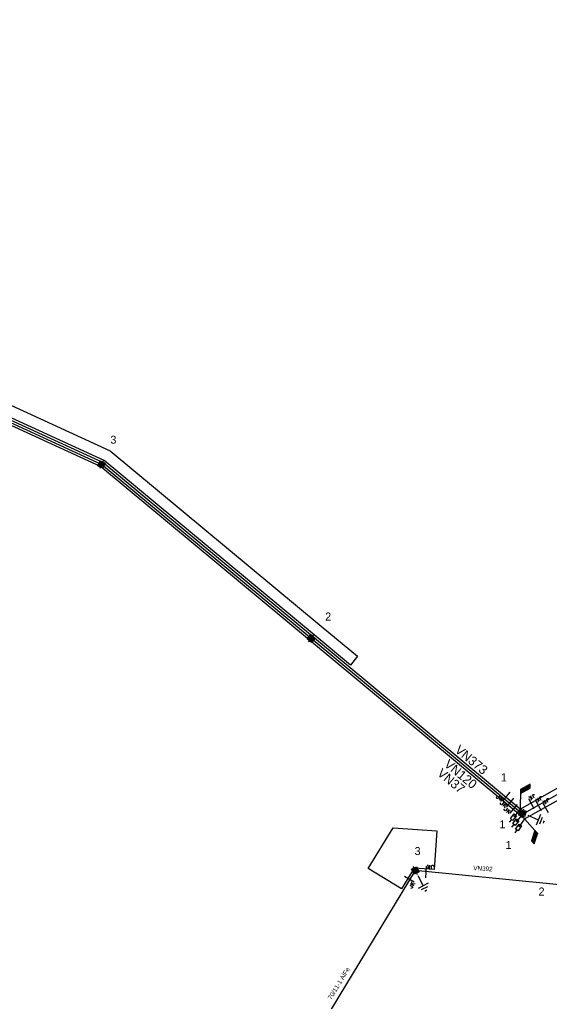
# Model space of a CAD drawing. Extents: x -540340 to -537226, y -1183949 to -1180375.
# Drawn here: x -537658.9 to -537543.1, y -1180690 to -1180475.4 of the extents above; entities that cross this region are included whole.
import ezdxf

# ---------------------------------------------------------------- set-up
doc = ezdxf.new("R2010")
doc.units = 0
for name, color, linetype in [('Vrstva 1', 7, 'Continuous'), ('Vrstva 11', 7, 'Continuous'), ('Vrstva 12', 7, 'Continuous'), ('Vrstva 13', 7, 'Continuous'), ('Vrstva 14', 7, 'Continuous'), ('Vrstva 15', 7, 'Continuous'), ('Vrstva 16', 7, 'Continuous'), ('Vrstva 18', 7, 'Continuous'), ('Vrstva 2', 7, 'Continuous'), ('Vrstva 3', 7, 'Continuous'), ('Vrstva 35', 7, 'Continuous'), ('Vrstva 50', 7, 'Continuous'), ('Vrstva 51', 7, 'Continuous')]:
    doc.layers.add(name, color=color, linetype=linetype)

msp = doc.modelspace()

# ---------------------------------------------------------------- linework, layer by layer
at = {"layer": 'Vrstva 1'}
for points in [[(-537549.42, -1180647.98), (-537524.99, -1180634.15)], [(-537548.92, -1180649.04), (-537524.29, -1180635.07)], [(-537548.49, -1180650.05), (-537523.4, -1180636.11)], [(-537531.99, -1180665.41), (-537572.36, -1180661.38), (-537627.26, -1180751.9)]]:
    msp.add_lwpolyline(points, dxfattribs=at)
at = {"layer": 'Vrstva 11'}
for p, q in [((-537549.38, -1180644.32), (-537547.27, -1180643.15)), ((-537549.38, -1180644.37), (-537547.27, -1180643.2)), ((-537549.38, -1180644.43), (-537547.27, -1180643.26)), ((-537549.38, -1180644.49), (-537547.27, -1180643.32)), ((-537549.37, -1180643.74), (-537547.26, -1180642.57)), ((-537549.37, -1180643.8), (-537547.26, -1180642.63)), ((-537549.37, -1180643.86), (-537547.26, -1180642.68)), ((-537549.37, -1180643.91), (-537547.26, -1180642.74)), ((-537549.37, -1180643.97), (-537547.26, -1180642.8)), ((-537549.37, -1180644.03), (-537547.26, -1180642.86)), ((-537549.37, -1180644.09), (-537547.26, -1180642.91)), ((-537549.37, -1180644.14), (-537547.26, -1180642.97)), ((-537549.37, -1180644.2), (-537547.26, -1180643.03)), ((-537549.37, -1180644.26), (-537547.26, -1180643.09)), ((-537549.37, -1180643.68), (-537549.01, -1180643.48)), ((-537546.17, -1180652.66), (-537546.94, -1180654.95)), ((-537546.13, -1180652.7), (-537546.9, -1180654.99)), ((-537546.09, -1180652.74), (-537546.86, -1180655.03)), ((-537546.06, -1180652.79), (-537546.82, -1180655.08)), ((-537546.02, -1180652.83), (-537546.79, -1180655.12)), ((-537545.98, -1180652.87), (-537546.75, -1180655.16)), ((-537545.94, -1180652.92), (-537546.71, -1180655.21)), ((-537545.9, -1180652.96), (-537546.67, -1180655.25)), ((-537545.86, -1180653), (-537546.63, -1180655.29)), ((-537545.83, -1180653.05), (-537546.6, -1180655.33)), ((-537545.79, -1180653.09), (-537546.56, -1180655.38)), ((-537545.75, -1180653.13), (-537546.52, -1180655.42)), ((-537545.71, -1180653.17), (-537546.48, -1180655.46)), ((-537545.67, -1180653.22), (-537546.44, -1180655.51)), ((-537545.64, -1180653.26), (-537545.77, -1180653.65))]:
    msp.add_line(p, q, dxfattribs=at)
for points in [[(-537549.37, -1180643.68), (-537549.42, -1180647.98)], [(-537545.63, -1180653.26), (-537548.49, -1180650.05)]]:
    msp.add_lwpolyline(points, dxfattribs=at)
for points in [[(-537547.25, -1180642.52), (-537549.37, -1180643.68), (-537549.38, -1180644.54), (-537547.27, -1180643.37)], [(-537546.41, -1180655.55), (-537545.63, -1180653.26), (-537546.21, -1180652.62), (-537546.97, -1180654.91)]]:
    msp.add_lwpolyline(points, close=True, dxfattribs=at)
at = {"layer": 'Vrstva 13'}
for points in [[(-537641.74, -1180572.92), (-537641.23, -1180571.8)], [(-537640.63, -1180573.43), (-537641.74, -1180572.92)], [(-537641.54, -1180572.85), (-537641.16, -1180572.01)], [(-537640.71, -1180573.23), (-537641.54, -1180572.85)], [(-537641.34, -1180572.76), (-537641.08, -1180572.21)], [(-537640.78, -1180573.02), (-537641.34, -1180572.76)], [(-537641.19, -1180573.17), (-537641.34, -1180573.51)], [(-537641.23, -1180571.8), (-537640.12, -1180572.31)], [(-537641.16, -1180572.01), (-537640.32, -1180572.4)], [(-537641.12, -1180572.67), (-537641, -1180572.39)], [(-537640.85, -1180572.8), (-537641.12, -1180572.67)], [(-537641.08, -1180572.21), (-537640.52, -1180572.46)], [(-537641, -1180572.39), (-537640.72, -1180572.52)], [(-537640.72, -1180572.52), (-537640.85, -1180572.8)], [(-537640.52, -1180572.46), (-537640.78, -1180573.02)], [(-537640.32, -1180572.4), (-537640.71, -1180573.23)], [(-537640.67, -1180572.06), (-537640.52, -1180571.72)], [(-537640.12, -1180572.31), (-537640.63, -1180573.43)], [(-537596.01, -1180610.73), (-537595.22, -1180609.78)], [(-537595.8, -1180610.72), (-537595.21, -1180610.01)], [(-537595.22, -1180609.78), (-537594.28, -1180610.57)], [(-537595.21, -1180610.01), (-537594.5, -1180610.6)], [(-537594.75, -1180610.18), (-537594.51, -1180609.89)], [(-537595.06, -1180611.51), (-537596.01, -1180610.73)], [(-537595.09, -1180611.31), (-537595.8, -1180610.72)], [(-537595.54, -1180611.12), (-537595.78, -1180611.41)], [(-537595.58, -1180610.69), (-537595.18, -1180610.22)], [(-537595.1, -1180611.08), (-537595.58, -1180610.69)], [(-537595.35, -1180610.65), (-537595.15, -1180610.42)], [(-537595.11, -1180610.85), (-537595.35, -1180610.65)], [(-537595.18, -1180610.22), (-537594.71, -1180610.61)], [(-537595.15, -1180610.42), (-537594.92, -1180610.61)], [(-537594.92, -1180610.61), (-537595.11, -1180610.85)], [(-537594.71, -1180610.61), (-537595.1, -1180611.08)], [(-537594.5, -1180610.6), (-537595.09, -1180611.31)], [(-537594.28, -1180610.57), (-537595.06, -1180611.51)], [(-537549.7, -1180649.25), (-537549.34, -1180648.07)], [(-537549.51, -1180649.16), (-537549.24, -1180648.27)], [(-537549.34, -1180648.07), (-537548.16, -1180648.43)], [(-537549.31, -1180649.04), (-537549.13, -1180648.46)], [(-537549.24, -1180648.27), (-537548.36, -1180648.54)], [(-537549.13, -1180648.46), (-537548.55, -1180648.64)], [(-537549.12, -1180648.92), (-537549.03, -1180648.63)], [(-537549.03, -1180648.63), (-537548.73, -1180648.72)], [(-537548.73, -1180648.72), (-537548.82, -1180649.01)], [(-537548.75, -1180648.25), (-537548.64, -1180647.89)], [(-537548.55, -1180648.64), (-537548.73, -1180649.22)], [(-537548.36, -1180648.54), (-537548.63, -1180649.42)], [(-537548.16, -1180648.43), (-537548.52, -1180649.61)], [(-537548.52, -1180649.61), (-537549.7, -1180649.25)], [(-537548.63, -1180649.42), (-537549.51, -1180649.16)], [(-537548.73, -1180649.22), (-537549.31, -1180649.04)], [(-537549.11, -1180649.43), (-537549.22, -1180649.79)], [(-537548.82, -1180649.01), (-537549.12, -1180648.92)], [(-537573.18, -1180661.11), (-537572.08, -1180660.56)], [(-537572.63, -1180662.2), (-537573.18, -1180661.11)], [(-537572.97, -1180661.18), (-537572.15, -1180660.77)], [(-537572.56, -1180662.01), (-537572.97, -1180661.18)], [(-537572.63, -1180660.83), (-537572.8, -1180660.5)], [(-537572.77, -1180661.24), (-537572.22, -1180660.97)], [(-537572.5, -1180661.79), (-537572.77, -1180661.24)], [(-537572.57, -1180661.29), (-537572.3, -1180661.16)], [(-537572.44, -1180661.57), (-537572.57, -1180661.29)], [(-537571.74, -1180661.59), (-537572.56, -1180662.01)], [(-537571.95, -1180661.52), (-537572.5, -1180661.79)], [(-537572.16, -1180661.43), (-537572.44, -1180661.57)], [(-537572.3, -1180661.16), (-537572.16, -1180661.43)], [(-537572.22, -1180660.97), (-537571.95, -1180661.52)], [(-537572.15, -1180660.77), (-537571.74, -1180661.59)], [(-537572.08, -1180660.56), (-537571.53, -1180661.65)], [(-537571.53, -1180661.65), (-537572.63, -1180662.2)], [(-537572.08, -1180661.93), (-537571.92, -1180662.26)]]:
    msp.add_lwpolyline(points, dxfattribs=at)
at = {"layer": 'Vrstva 15'}
for points in [[(-537547.78, -1180649.31), (-537545.47, -1180650.27)], [(-537544.99, -1180649.12), (-537545.95, -1180651.43)], [(-537544.6, -1180649.8), (-537545.21, -1180651.26)], [(-537544.31, -1180650.75), (-537544.41, -1180650.99)], [(-537544.21, -1180650.51), (-537544.31, -1180650.75)], [(-537571.79, -1180662.49), (-537570.65, -1180664.71)], [(-537569.54, -1180664.14), (-537571.76, -1180665.28)], [(-537569.68, -1180664.91), (-537571.09, -1180665.63)], [(-537570.08, -1180665.82), (-537570.31, -1180665.94)], [(-537569.84, -1180665.7), (-537570.08, -1180665.82)]]:
    msp.add_lwpolyline(points, dxfattribs=at)
at = {"layer": 'Vrstva 16'}
for points in [[(-537549.42, -1180647.98), (-537550.78, -1180649.58)], [(-537551.33, -1180650.23), (-537551.85, -1180650.84)], [(-537551.58, -1180650.02), (-537550.72, -1180649.01)], [(-537551.08, -1180650.45), (-537551.58, -1180650.02)], [(-537550.22, -1180649.44), (-537551.08, -1180650.45)], [(-537551.06, -1180651.11), (-537550.21, -1180650.1)], [(-537550.78, -1180649.58), (-537550.71, -1180649.32)], [(-537550.78, -1180649.58), (-537550.53, -1180649.47)], [(-537550.72, -1180649.01), (-537550.22, -1180649.44)], [(-537549.71, -1180650.52), (-537550.55, -1180651.53)], [(-537548.92, -1180649.05), (-537550.26, -1180650.67)], [(-537550.26, -1180650.67), (-537550.2, -1180650.4)], [(-537550.26, -1180650.67), (-537550.02, -1180650.55)], [(-537550.21, -1180650.1), (-537549.71, -1180650.52)], [(-537548.49, -1180650.05), (-537549.68, -1180651.79)], [(-537550.81, -1180651.32), (-537551.31, -1180651.93)], [(-537550.55, -1180651.53), (-537551.06, -1180651.11)], [(-537550.15, -1180652.49), (-537550.6, -1180653.15)], [(-537550.42, -1180652.31), (-537549.68, -1180651.22)], [(-537549.88, -1180652.68), (-537550.42, -1180652.31)], [(-537549.13, -1180651.59), (-537549.88, -1180652.68)], [(-537549.68, -1180651.22), (-537549.13, -1180651.59)], [(-537549.68, -1180651.79), (-537549.64, -1180651.52)], [(-537549.68, -1180651.79), (-537549.44, -1180651.66)]]:
    msp.add_lwpolyline(points, dxfattribs=at)
at = {"layer": 'Vrstva 18'}
for points in [[(-537551.73, -1180644.22), (-537553.33, -1180646.14)], [(-537554.63, -1180645.41), (-537554.58, -1180645.31)], [(-537554.56, -1180645.56), (-537554.63, -1180645.41)], [(-537554.58, -1180645.31), (-537554.52, -1180645.23)], [(-537554.51, -1180645.6), (-537554.56, -1180645.56)], [(-537554.36, -1180645.63), (-537554.51, -1180645.6)], [(-537554.26, -1180645.57), (-537554.36, -1180645.63)], [(-537553.85, -1180645.07), (-537554.26, -1180645.57)], [(-537553.53, -1180645.34), (-537554.06, -1180645.97)], [(-537553.86, -1180645.73), (-537553.21, -1180645.6)], [(-537553.65, -1180645.69), (-537553.69, -1180646.28)], [(-537552.99, -1180646.44), (-537553.4, -1180646.94)], [(-537550.87, -1180645.59), (-537552.47, -1180647.51)], [(-537547.03, -1180645.55), (-537547.57, -1180645.3)], [(-537546.34, -1180647.86), (-537547.57, -1180645.68)], [(-537546.74, -1180645.78), (-537547.15, -1180645.06)], [(-537546.99, -1180645.34), (-537547.1, -1180645.98)], [(-537546.72, -1180644.9), (-537546.64, -1180644.77)], [(-537546.7, -1180645.01), (-537546.72, -1180644.9)], [(-537546.38, -1180645.58), (-537546.7, -1180645.01)], [(-537546.64, -1180644.77), (-537546.58, -1180644.74)], [(-537546.58, -1180644.74), (-537546.42, -1180644.73)], [(-537546.42, -1180644.73), (-537546.34, -1180644.81)], [(-537546.34, -1180644.81), (-537546.29, -1180644.89)], [(-537545.48, -1180646.01), (-537546.01, -1180645.76)], [(-537544.78, -1180648.32), (-537546.01, -1180646.15)], [(-537545.19, -1180646.24), (-537545.59, -1180645.52)], [(-537545.44, -1180645.8), (-537545.55, -1180646.45)], [(-537545.17, -1180645.36), (-537545.08, -1180645.23)], [(-537545.15, -1180645.48), (-537545.17, -1180645.36)], [(-537544.83, -1180646.04), (-537545.15, -1180645.48)], [(-537545.08, -1180645.23), (-537545.03, -1180645.2)], [(-537545.03, -1180645.2), (-537544.87, -1180645.19)], [(-537544.87, -1180645.19), (-537544.79, -1180645.27)], [(-537544.79, -1180645.27), (-537544.74, -1180645.36)], [(-537543.95, -1180646.46), (-537544.49, -1180646.2)], [(-537543.27, -1180648.77), (-537544.49, -1180646.58)], [(-537543.66, -1180646.69), (-537544.06, -1180645.97)], [(-537543.91, -1180646.24), (-537544.02, -1180646.89)], [(-537543.64, -1180645.81), (-537543.55, -1180645.68)], [(-537543.62, -1180645.92), (-537543.64, -1180645.81)], [(-537543.3, -1180646.49), (-537543.62, -1180645.92)], [(-537543.55, -1180645.68), (-537543.5, -1180645.65)], [(-537543.5, -1180645.65), (-537543.33, -1180645.64)], [(-537543.33, -1180645.64), (-537543.26, -1180645.72)], [(-537543.26, -1180645.72), (-537543.21, -1180645.81)], [(-537553.77, -1180646.78), (-537553.72, -1180646.68)], [(-537553.7, -1180646.93), (-537553.77, -1180646.78)], [(-537553.72, -1180646.68), (-537553.66, -1180646.6)], [(-537553.65, -1180646.96), (-537553.7, -1180646.93)], [(-537553.5, -1180647), (-537553.65, -1180646.96)], [(-537553.4, -1180646.94), (-537553.5, -1180647)], [(-537552.67, -1180646.71), (-537553.2, -1180647.34)], [(-537553, -1180647.1), (-537552.35, -1180646.97)], [(-537552.96, -1180648.1), (-537552.91, -1180648)], [(-537552.89, -1180648.25), (-537552.96, -1180648.1)], [(-537552.91, -1180648), (-537552.85, -1180647.92)], [(-537552.84, -1180648.29), (-537552.89, -1180648.25)], [(-537552.69, -1180648.32), (-537552.84, -1180648.29)], [(-537552.78, -1180647.06), (-537552.83, -1180647.65)], [(-537552.59, -1180648.26), (-537552.69, -1180648.32)], [(-537552.18, -1180647.76), (-537552.59, -1180648.26)], [(-537551.86, -1180648.03), (-537552.39, -1180648.66)], [(-537552.19, -1180648.42), (-537551.54, -1180648.29)], [(-537551.98, -1180648.38), (-537552.02, -1180648.97)], [(-537550.06, -1180646.91), (-537551.66, -1180648.83)], [(-537570.05, -1180662.96), (-537569.88, -1180660.46)], [(-537569.36, -1180660.65), (-537569.67, -1180660.14)], [(-537569.21, -1180660.49), (-537569.66, -1180660.97)], [(-537569.25, -1180661), (-537569.19, -1180660.17)], [(-537568.83, -1180661.03), (-537568.79, -1180660.38)], [(-537568.79, -1180660.38), (-537568.74, -1180660.27)], [(-537568.74, -1180660.27), (-537568.6, -1180660.21)], [(-537568.6, -1180660.21), (-537568.54, -1180660.22)], [(-537568.54, -1180660.22), (-537568.4, -1180660.3)], [(-537568.4, -1180660.3), (-537568.38, -1180660.41)], [(-537568.38, -1180660.41), (-537568.38, -1180660.5)], [(-537574.75, -1180662.59), (-537572.61, -1180663.88)], [(-537573.59, -1180664.56), (-537573.04, -1180664.89)], [(-537573.38, -1180664.2), (-537572.67, -1180664.63)], [(-537573.25, -1180665.25), (-537573.33, -1180665.19)], [(-537573.14, -1180665.28), (-537573.25, -1180665.25)], [(-537572.94, -1180664.47), (-537573.16, -1180663.85)], [(-537573.01, -1180665.19), (-537573.14, -1180665.28)], [(-537573.04, -1180664.89), (-537572.96, -1180664.98)], [(-537573.01, -1180664.26), (-537572.42, -1180664.22)], [(-537572.98, -1180665.14), (-537573.01, -1180665.19)], [(-537572.96, -1180664.98), (-537572.98, -1180665.14)]]:
    msp.add_lwpolyline(points, dxfattribs=at)
at = {"layer": 'Vrstva 35'}
for points in [[(-537586.56, -1180616.48), (-537594.5, -1180609.88), (-537640.39, -1180571.76), (-537698.73, -1180545.01), (-537770.01, -1180529.36), (-537769.48, -1180526.92), (-537697.93, -1180542.63), (-537639.05, -1180569.62), (-537592.91, -1180607.96), (-537584.96, -1180614.55)], [(-537575.36, -1180665.36), (-537582.63, -1180660.96), (-537577.21, -1180652.03), (-537567.62, -1180652.68), (-537568.2, -1180661.16), (-537572.63, -1180660.86)]]:
    msp.add_lwpolyline(points, close=True, dxfattribs=at)
at = {"layer": 'Vrstva 50'}
for points in [[(-537549.42, -1180647.98), (-537594.82, -1180610.26), (-537640.66, -1180572.18), (-537698.89, -1180545.49), (-537770.12, -1180529.84), (-537817.09, -1180530.41), (-537899.91, -1180516.71), (-537967.43, -1180502.43), (-538028.9, -1180486.5), (-538083.27, -1180475.39)], [(-537548.92, -1180649.05), (-537595.14, -1180610.65), (-537640.93, -1180572.61), (-537699.05, -1180545.96), (-537770.17, -1180530.35), (-537817.13, -1180530.91), (-537900, -1180517.2), (-537967.54, -1180502.92), (-538029.01, -1180486.99), (-538083.27, -1180475.98)], [(-537548.49, -1180650.05), (-537595.46, -1180611.03), (-537641.2, -1180573.04), (-537699.21, -1180546.44), (-537770.22, -1180530.85), (-537817.17, -1180531.41), (-537900.09, -1180517.69), (-537967.65, -1180503.41), (-538029.12, -1180487.48), (-538083.26, -1180476.62)]]:
    msp.add_lwpolyline(points, dxfattribs=at)

# ---------------------------------------------------------------- texts
at = {"layer": 'Vrstva 12'}
for s, p in [('1', (-537553.65, -1180641.9)), ('1', (-537552.62, -1180656.67)), ('2', (-537545.41, -1180666.84))]:
    msp.add_text(s, height=1.75, dxfattribs=at).set_placement(p)
at = {"layer": 'Vrstva 14'}
for s, p in [('3', (-537639.01, -1180568.09)), ('2', (-537592.05, -1180606.73)), ('1', (-537553.96, -1180652.13)), ('3', (-537572.51, -1180658))]:
    msp.add_text(s, height=1.75, dxfattribs=at).set_placement(p)
at = {"layer": 'Vrstva 2'}
msp.add_text('70/11-1 AlFe', height=1, rotation=58.763, dxfattribs=at).set_placement((-537590.71, -1180689.69))
at = {"layer": 'Vrstva 3'}
msp.add_text('VN392', height=1, rotation=356.122, dxfattribs=at).set_placement((-537559.71, -1180661.29))
at = {"layer": 'Vrstva 51'}
for s, p in [('VN373', (-537563.87, -1180635.33)), ('VN120', (-537566.22, -1180638.44)), ('VN37', (-537567.72, -1180640.4))]:
    msp.add_text(s, height=2, rotation=320.281, dxfattribs=at).set_placement(p)

doc.saveas('drawing.dxf')
